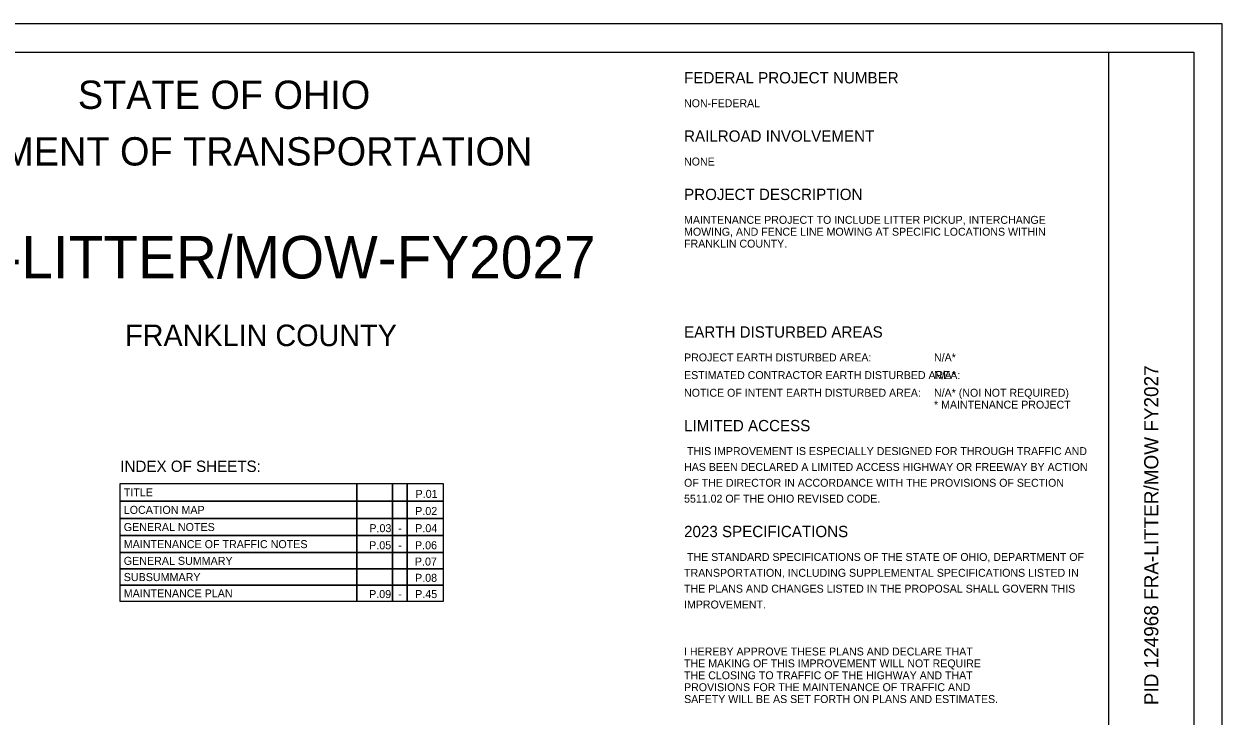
# Model space of a CAD drawing. Extents: x 0 to 34, y 0 to 22.
# Drawn here: x 12.84 to 34, y 9.78 to 22 of the extents above; entities that cross this region are included whole.
import ezdxf

# ---------------------------------------------------------------- set-up
doc = ezdxf.new("R2010")
doc.units = 0
for name, color, linetype in [('Default', 7, 'Continuous'), ('SH_Border', 7, 'Continuous'), ('SH_Cut_Line', 7, 'Continuous'), ('SH_Data', 7, 'Continuous'), ('SH_Text', 7, 'Continuous')]:
    doc.layers.add(name, color=color, linetype=linetype)

msp = doc.modelspace()

# ---------------------------------------------------------------- linework, layer by layer
at = {"layer": 'Default'}
for points in [[(14.544, 13.886), (18.718, 13.886), (18.718, 13.569), (14.544, 13.569)], [(18.718, 13.886), (19.353, 13.886), (19.353, 13.569), (18.718, 13.569)], [(19.353, 13.886), (19.61, 13.886), (19.61, 13.569), (19.353, 13.569)], [(19.61, 13.886), (20.245, 13.886), (20.245, 13.569), (19.61, 13.569)], [(14.544, 13.569), (18.718, 13.569), (18.718, 13.266), (14.544, 13.266)], [(18.718, 13.569), (19.353, 13.569), (19.353, 13.266), (18.718, 13.266)], [(19.353, 13.569), (19.61, 13.569), (19.61, 13.266), (19.353, 13.266)], [(19.61, 13.569), (20.245, 13.569), (20.245, 13.266), (19.61, 13.266)], [(14.544, 13.266), (18.718, 13.266), (18.718, 12.964), (14.544, 12.964)], [(18.718, 13.266), (19.353, 13.266), (19.353, 12.964), (18.718, 12.964)], [(19.353, 13.266), (19.61, 13.266), (19.61, 12.964), (19.353, 12.964)], [(19.61, 13.266), (20.245, 13.266), (20.245, 12.964), (19.61, 12.964)], [(14.544, 12.964), (18.718, 12.964), (18.718, 12.662), (14.544, 12.662)], [(18.718, 12.964), (19.353, 12.964), (19.353, 12.662), (18.718, 12.662)], [(19.353, 12.964), (19.61, 12.964), (19.61, 12.662), (19.353, 12.662)], [(19.61, 12.964), (20.245, 12.964), (20.245, 12.662), (19.61, 12.662)], [(14.544, 12.662), (18.718, 12.662), (18.718, 12.374), (14.544, 12.374)], [(18.718, 12.662), (19.353, 12.662), (19.353, 12.374), (18.718, 12.374)], [(19.353, 12.662), (19.61, 12.662), (19.61, 12.374), (19.353, 12.374)], [(19.61, 12.662), (20.245, 12.662), (20.245, 12.374), (19.61, 12.374)], [(14.544, 12.374), (18.718, 12.374), (18.718, 12.087), (14.544, 12.087)], [(18.718, 12.374), (19.353, 12.374), (19.353, 12.087), (18.718, 12.087)], [(19.353, 12.374), (19.61, 12.374), (19.61, 12.087), (19.353, 12.087)], [(19.61, 12.374), (20.245, 12.374), (20.245, 12.087), (19.61, 12.087)], [(14.544, 12.087), (18.718, 12.087), (18.718, 11.8), (14.544, 11.8)], [(18.718, 12.087), (19.353, 12.087), (19.353, 11.8), (18.718, 11.8)], [(19.353, 12.087), (19.61, 12.087), (19.61, 11.8), (19.353, 11.8)], [(19.61, 12.087), (20.245, 12.087), (20.245, 11.8), (19.61, 11.8)]]:
    msp.add_lwpolyline(points, close=True, dxfattribs=at)
at = {"layer": 'SH_Border'}
msp.add_line((32, 0.5), (32, 21.5), dxfattribs=at)
msp.add_lwpolyline([(1.5, 21.5), (33.5, 21.5), (33.5, 0.5), (1.5, 0.5)], close=True, dxfattribs=at)
at = {"layer": 'SH_Cut_Line'}
msp.add_lwpolyline([(0, 0), (34, 0), (34, 22), (0, 22)], close=True, dxfattribs=at)
at = {"layer": 'SH_Data'}
for p, q in [((24.5, 14.526), (24.5, 14.526)), ((24.5, 10.986), (24.5, 10.986))]:
    msp.add_line(p, q, dxfattribs=at)

# ---------------------------------------------------------------- texts
at = {"layer": 'Default'}
for s, p in [('I HEREBY APPROVE THESE PLANS AND DECLARE THAT', (24.5, 10.846)), ('THE MAKING OF THIS IMPROVEMENT WILL NOT REQUIRE', (24.5, 10.636)), ('THE CLOSING TO TRAFFIC OF THE HIGHWAY AND THAT', (24.5, 10.426)), ('PROVISIONS FOR THE MAINTENANCE OF TRAFFIC AND', (24.5, 10.216)), ('SAFETY WILL BE AS SET FORTH ON PLANS AND ESTIMATES.', (24.5, 10.006))]:
    msp.add_text(s, height=0.14, dxfattribs=at).set_placement(p)
at = {"layer": 'SH_Data'}
msp.add_text('PID 124968 FRA-LITTER/MOW FY2027', height=0.25, rotation=90, dxfattribs=at).set_placement((32.875, 9.969))
at = {"layer": 'SH_Text'}
for s, height, p in [('STATE OF OHIO', 0.5, (13.795, 20.5)), ('FEDERAL PROJECT NUMBER', 0.2, (24.5, 20.95)), ('NON-FEDERAL', 0.14, (24.5, 20.53)), ('RAILROAD INVOLVEMENT', 0.2, (24.5, 19.92)), ('DEPARTMENT OF TRANSPORTATION', 0.5, (9.747, 19.5)), ('NONE', 0.14, (24.5, 19.5)), ('PROJECT DESCRIPTION', 0.2, (24.5, 18.89)), ('MAINTENANCE PROJECT TO INCLUDE LITTER PICKUP, INTERCHANGE ', 0.14, (24.5, 18.47)), ('FRA-LITTER/MOW-FY2027', 0.75, (10.455, 17.505)), ('MOWING, AND FENCE LINE MOWING AT SPECIFIC LOCATIONS WITHIN ', 0.14, (24.5, 18.26)), ('FRANKLIN COUNTY.', 0.14, (24.5, 18.05)), ('FRANKLIN COUNTY', 0.38, (14.629, 16.31)), ('EARTH DISTURBED AREAS', 0.2, (24.5, 16.46)), ('PROJECT EARTH DISTURBED AREA:', 0.14, (24.5, 16.04)), ('N/A*', 0.14, (28.914, 16.04)), ('ESTIMATED CONTRACTOR EARTH DISTURBED AREA:', 0.14, (24.5, 15.728)), ('N/A*', 0.14, (28.914, 15.728)), ('NOTICE OF INTENT EARTH DISTURBED AREA:', 0.14, (24.5, 15.416)), ('N/A* (NOI NOT REQUIRED)', 0.14, (28.914, 15.416)), ('* MAINTENANCE PROJECT', 0.14, (28.914, 15.206)), ('LIMITED ACCESS', 0.2, (24.5, 14.806)), (' THIS IMPROVEMENT IS ESPECIALLY DESIGNED FOR THROUGH TRAFFIC AND', 0.14, (24.5, 14.386)), ('INDEX OF SHEETS:', 0.2, (14.544, 14.088)), ('HAS BEEN DECLARED A LIMITED ACCESS HIGHWAY OR FREEWAY BY ACTION', 0.14, (24.5, 14.106)), ('OF THE DIRECTOR IN ACCORDANCE WITH THE PROVISIONS OF SECTION', 0.14, (24.5, 13.826)), ('TITLE', 0.1414, (14.605, 13.657)), ('P.01', 0.1414, (19.758, 13.629)), ('5511.02 OF THE OHIO REVISED CODE.', 0.14, (24.5, 13.546)), ('LOCATION MAP', 0.14137, (14.605, 13.347)), ('P.02', 0.1414, (19.752, 13.327)), ('GENERAL NOTES', 0.14137, (14.605, 13.044)), ('P.03', 0.1414, (18.942, 13.024)), ('P.04', 0.1414, (19.752, 13.024)), ('2023 SPECIFICATIONS', 0.2, (24.5, 12.936)), ('-', 0.141, (19.453, 13.024)), ('MAINTENANCE OF TRAFFIC NOTES', 0.14137, (14.605, 12.742)), ('P.05', 0.1414, (18.939, 12.722)), ('-', 0.141, (19.453, 12.722)), ('P.06', 0.1414, (19.748, 12.722)), ('GENERAL SUMMARY', 0.14137, (14.605, 12.447)), ('P.07', 0.1414, (19.746, 12.435)), (' THE STANDARD SPECIFICATIONS OF THE STATE OF OHIO, DEPARTMENT OF ', 0.14, (24.5, 12.516)), ('SUBSUMMARY', 0.1414, (14.605, 12.16)), ('P.08', 0.1414, (19.749, 12.147)), ('TRANSPORTATION, INCLUDING SUPPLEMENTAL SPECIFICATIONS LISTED IN ', 0.14, (24.5, 12.236)), ('THE PLANS AND CHANGES LISTED IN THE PROPOSAL SHALL GOVERN THIS ', 0.14, (24.5, 11.956)), ('MAINTENANCE PLAN', 0.14137, (14.605, 11.873)), ('P.09', 0.1414, (18.938, 11.86)), ('-', 0.141, (19.453, 11.86)), ('P.45', 0.1414, (19.751, 11.86)), ('IMPROVEMENT.', 0.14, (24.5, 11.676))]:
    msp.add_text(s, height=height, dxfattribs=at).set_placement(p)

doc.saveas('drawing.dxf')
